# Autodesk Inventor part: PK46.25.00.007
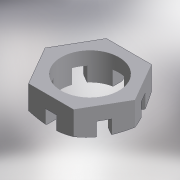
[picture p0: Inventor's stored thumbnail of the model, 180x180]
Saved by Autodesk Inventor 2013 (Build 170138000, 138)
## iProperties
Shininess: 25.0
Length Units: 11269
Angle Units: 11279
Time Units: 11290
Mass Units: 11283
Length Display Precision: 3
Angle Display Precision: 2
Created: 2001-04
Part Number: PK46.25.00.007
Material: Steel, Mild
Description: Гайка М14-6Н.8.019 ГОСТ 5932-73
Document SubType Name: Modeling
Designer: tevgeniy
Density: 7.86 g/cm^3
Density: 0.0
Volumn: 0.0
Area: 0.0
PropertySet Name: Model Information
Control State: 0
Master: False
Checked Out: True
Checked Out Date: 2008-10-15
Last Check In Date: 2008-10-15
Author: tevgeniy
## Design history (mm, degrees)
node "ExtrusionBlind1" dims "d6" = 25, "d7" = 0
  sketch "Sketch1"
    geometry: L1 (514.989, 469.325)-(474.575, 469.325); L2 (535.196, 434.325)-(514.989, 469.325); L3 (514.989, 399.325)-(535.196, 434.325); L4 (474.575, 399.325)-(514.989, 399.325); L5 (454.367, 434.325)-(474.575, 399.325); L6 (474.575, 469.325)-(454.367, 434.325); C1 r 35 at (494.782, 434.325)
    constraints: 12 end point, 6 tangent, 3 parallel, 1 centre point, 1 horizontal, 1 other
    dimensions: "d1" = 120 deg angle of L1 L2; "d3" = 120 deg angle of L5 L6; "d5" = 70 diameter of C1; "d29" = 70 distance between parallel lines of L1 L4 (derived)
node "ExtrusionThru1" dims "d14" = 0.13, "d15" = 0
  sketch "Sketch2"
    geometry: L1 (-476.374, -396.209)-(-475.874, -397.075); L2 (-503.696, -391.412)-(-503.261, -390.917); L3 (-516.411, -401.787)-(-515.911, -400.921); L4 (-514.989, -469.325)-(-535.196, -434.325) reference; L5 (-474.575, -469.325)-(-514.989, -469.325) reference; L6 (-454.367, -434.325)-(-474.575, -469.325) reference; L7 (-474.575, -399.325)-(-454.367, -434.325) reference; L8 (-514.989, -399.325)-(-474.575, -399.325) reference; L9 (-535.196, -434.325)-(-514.989, -399.325) reference; C1 r 26 at (-494.782, -434.325); C2 r 35 at (-494.782, -434.325)
    constraints: 6 end point, 6 tangent, 2 centre point, 1 coincident
    dimensions: "d13" = 52 diameter of C1
node "WorkAxis1"
node "WorkPlane1"
node "RevolutionFull1" dims "d24" = 360 deg
  sketch "Sketch3"
    geometry: L1 (0, 0)-(0, 25); L2 (34, 0)-(0, 0); L3 (40.415, 3.703)-(34, 0); L4 (40.415, 21.297)-(40.415, 3.703); L5 (34, 25)-(40.415, 21.297); L6 (0, 25)-(34, 25); L7 (0, 25)-(0.223, 25); L8 (-27.612, 0)-(-28.612, 0); L9 (40.415, 2.43)-(40.415, 1.43); L10 (0, 15.645)-(0, -15.645); L11 (0, 15.645)-(0, -15.645); L12 (20.207, 25)-(-20.207, 25) reference; L13 (-20.207, 0)-(20.207, 0) reference; L14 (0, -23.774)-(0, 33.129) reference; L15 (40.415, 25)-(40.415, 0) reference; L16 (34, 25)-(40.415, 25); L17 (40.415, 21.297)-(40.415, 25)
    constraints: 26 end point, 8 collinear, 3 horizontal, 3 vertical
    dimensions: "d17" = 34 distance of L1.end L5.start; "d19" = 30 deg angle of L6 L5; "d21" = 30 deg angle of L3 L2; "d23" = 0 horizontal distance of L5.start L2.start
sketch "Эскиз4"
  geometry: L1 (13.793, -3.703)-(-54.207, -3.703) reference; L2 (-25.207, -3.703)-(-15.207, -3.703); L3 (-15.207, -3.703)-(-15.207, 9.297); L4 (-15.207, 9.297)-(-25.207, 9.297); L5 (-25.207, 9.297)-(-25.207, -3.703); L6 (-20.207, -11.259)-(-20.207, 26.723) reference; L7 (0, 21.297)-(-40.415, 21.297) reference
  constraints: 8 end point, 2 parallel, 1 horizontal, 1 perpendicular, 1 point on line
  dimensions: "d32" = 10 distance of L3.end L4.end; "d33" = 5 distance between parallel lines of L5 L6 (= 0.5 x d32); "d39" = 12 distance between parallel lines of L4 L7
extrude "Выдавливание3" cut sketch "Эскиз4" stored distance "d34" = 10; taper "d35" = 0 deg
pattern_circular "Круговой массив1" dims angle "d38" = 360 deg
body "Solid1"
node "Спроецированная петля1"
other parameters: "d0" = 120 deg (derived), "d2" = 120 deg (derived), "d4" = 19 (derived), "d8" = 0, "d9" = 0, "d10" = 0, "d11" = 0, "d12" = 12 (derived), "d16" = 9 (derived), "d18" = 30 deg (derived), "d20" = 30 deg (derived), "d22" = 0 (derived)
